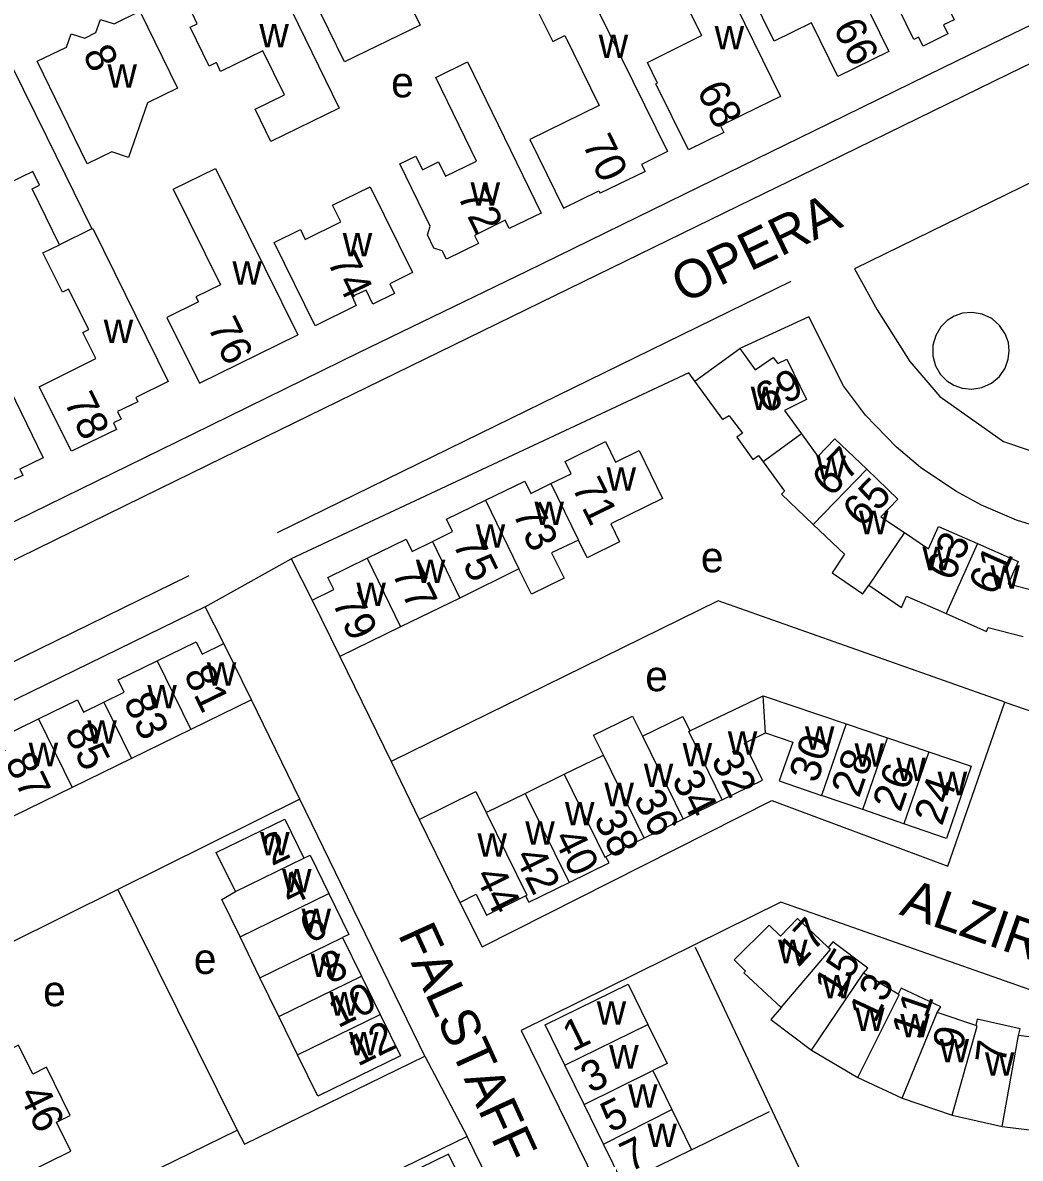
# Model space of a CAD drawing. Extents: x 159441 to 162086, y 388175 to 389787.
# Drawn here: x 161168.1 to 161298.8, y 389140.5 to 389289.4 of the extents above; entities that cross this region are included whole.
import ezdxf

# ---------------------------------------------------------------- set-up
doc = ezdxf.new("R2010")
doc.units = 0
for name, color, linetype in [('BLT_Basislijn', 7, 'Continuous'), ('BLT_Bebouwing', 7, 'Continuous'), ('BLT_Centroide', 7, 'Continuous'), ('BLT_Huisnummer', 7, 'Continuous'), ('BLT_Huisnummer_ tussenligend', 7, 'Continuous'), ('BLT_Huisnummer_reeks', 7, 'Continuous'), ('BLT_Onderverdeling_panden', 7, 'Continuous'), ('BLT_Straatnaam', 7, 'Continuous'), ('BLT_Vlakafsluiter', 7, 'Continuous')]:
    doc.layers.add(name, color=color, linetype=linetype)

msp = doc.modelspace()

# ---------------------------------------------------------------- linework, layer by layer
at = {"layer": 'BLT_Basislijn'}
for p, q in [((161201.47, 389222.55), (161268.78, 389255.48)), ((161216.38, 389192.52), (161220.02, 389184.92)), ((161256.18, 389168.15), (161275.7, 389126.74)), ((161220.77, 389153.85), (161226.34, 389143.34)), ((161255.73, 389141.61), (161265.95, 389146.61))]:
    msp.add_line(p, q, dxfattribs=at)
for points in [[(161323.97, 389300.63), (161318.56, 389298), (161310.41, 389294.03), (161297.83, 389287.9), (161288.73, 389283.48), (161273.69, 389276.11), (161254.7, 389266.85), (161234.08, 389256.77), (161212.19, 389246.11), (161190.3, 389235.4), (161162.94, 389222), (161151.75, 389216.52), (161143.27, 389212.36), (161140.82, 389211.17)], [(161140.82, 389211.17), (161141.32, 389210.26), (161142.12, 389209.17), (161142.71, 389208.49), (161143.97, 389207.61), (161153.84, 389212.52), (161186.03, 389228.29), (161194.27, 389232.34), (161235.94, 389252.69), (161261.89, 389265.34), (161273.46, 389270.99), (161297.32, 389282.66), (161308.2, 389287.97), (161328.14, 389297.72), (161329.19, 389298.24), (161330.33, 389298.66), (161331.64, 389299.08), (161333.15, 389299.34), (161334.55, 389299.5), (161335.85, 389299.5), (161337.31, 389299.35)], [(161356.55, 389242.65), (161339.94, 389276.6), (161339.22, 389277.83), (161338.54, 389278.75), (161337.48, 389279.77), (161336.36, 389280.67), (161334.32, 389281.67), (161332.32, 389282.19), (161330.34, 389282.27), (161328.28, 389281.94), (161326.76, 389281.41), (161277.06, 389257.08), (161280.07, 389251.72), (161284.35, 389244.96), (161288.25, 389240.35), (161296.6, 389234.45), (161306.3, 389231.2), (161315.37, 389230.18), (161324.36, 389231.75), (161328.63, 389233.02), (161339.19, 389236.54), (161356.55, 389242.65)], [(161297.36, 389246.34), (161297.24, 389247.44), (161296.83, 389248.59), (161296.1, 389249.69), (161295.06, 389250.58), (161293.8, 389251.17), (161292.48, 389251.39), (161291.22, 389251.27), (161290.14, 389250.89), (161289.23, 389250.32), (161288.39, 389249.48), (161287.72, 389248.38), (161287.35, 389247.07), (161287.34, 389245.68), (161287.71, 389244.37), (161288.36, 389243.26), (161289.2, 389242.42), (161290.11, 389241.84), (161291.19, 389241.46), (161292.44, 389241.33), (161293.77, 389241.54), (161295.03, 389242.11), (161296.07, 389243), (161296.82, 389244.09), (161297.23, 389245.24), (161297.36, 389246.34)], [(161377.7, 389141.03), (161398.49, 389150.98), (161358.19, 389233.53), (161324.94, 389222.58), (161320, 389221.7), (161315.37, 389221.36), (161310.96, 389221.46), (161306.93, 389221.92), (161302.1, 389222.95), (161298.33, 389224.14), (161293.71, 389226.11), (161290.34, 389227.93), (161285.72, 389231.07), (161282.57, 389233.73), (161278.51, 389237.91), (161275.64, 389241.75), (161271.11, 389250.82), (161262.06, 389246.64)], [(161256.17, 389242.38), (161255.39, 389243.46), (161203.26, 389219.06)], [(161203.26, 389219.06), (161206.03, 389213.65)], [(161100.59, 389173.15), (161115.84, 389180.62), (161189.89, 389216.88)], [(161191.99, 389212.77), (161117.83, 389176.55), (161130.41, 389150.79)], [(161194.44, 389207.98), (161191.99, 389212.77)], [(161296.77, 389200.28), (161259.21, 389213.58), (161216.38, 389192.52)], [(161209.65, 389206.25), (161216.38, 389192.52)], [(161204.39, 389187.56), (161198.06, 389200.58)], [(161225.36, 389174.03), (161228.3, 389168.2), (161266.25, 389187.37), (161289.33, 389178.76), (161296.77, 389200.28)], [(161296.77, 389200.28), (161311.63, 389195.19)], [(161204.39, 389187.56), (161180.56, 389175.71)], [(161220.77, 389153.85), (161204.39, 389187.56)], [(161180.56, 389175.71), (161130.41, 389150.79)], [(161180.56, 389175.71), (161196.2, 389144.16)], [(161329.32, 389134.03), (161317.5, 389156.46), (161267.42, 389174.06), (161233.39, 389157.24), (161255.69, 389111.86), (161258.43, 389113.03), (161264.05, 389102.15)], [(161197.16, 389142.32), (161220.77, 389153.85)], [(161145.7, 389119.49), (161196.2, 389144.16)], [(161196.2, 389144.16), (161197.16, 389142.32)], [(161226.34, 389143.34), (161201.39, 389131.17)], [(161231.96, 389069.61), (161256.48, 389081.57), (161226.34, 389143.34)]]:
    msp.add_lwpolyline(points, dxfattribs=at)
at = {"layer": 'BLT_Bebouwing'}
for p, q in [((161206.03, 389213.65), (161209.65, 389206.25)), ((161198.06, 389200.58), (161194.44, 389207.98)), ((161202.43, 389184.94), (161204.92, 389179.83)), ((161220.02, 389184.92), (161225.36, 389174.03)), ((161199.17, 389164.15), (161196.56, 389169.52)), ((161210.01, 389169.41), (161212.47, 389164.36)), ((161201.63, 389159.07), (161199.17, 389164.15)), ((161212.47, 389164.36), (161214.93, 389159.32)), ((161241.66, 389147.52), (161239.13, 389152.68)), ((161250.65, 389151.99), (161253.15, 389146.88)), ((161244.18, 389142.35), (161241.66, 389147.52))]:
    msp.add_line(p, q, dxfattribs=at)
for points in [[(161289.69, 389290.66), (161290.13, 389289.76), (161288.75, 389289.08), (161289.33, 389287.9), (161286.06, 389286.3), (161285.48, 389287.49), (161284.85, 389287.18), (161279.74, 389297.66), (161283.59, 389299.54), (161284.28, 389298.14), (161288.15, 389300.02), (161283.36, 389309.85), (161284.96, 389310.63), (161283.22, 389314.21), (161286.48, 389315.78)], [(161206.83, 389293), (161202.73, 389301.4), (161211.78, 389306.13), (161212.56, 389304.64), (161215.87, 389306.37), (161221.99, 389293.84), (161218.63, 389292.19), (161220.16, 389289.05), (161210.27, 389284.22), (161206.15, 389292.66), (161206.83, 389293)], [(161256.81, 389301.3), (161267.4, 389279.7), (161264.48, 389278.28), (161259.51, 389275.85), (161259.94, 389274.96), (161255.34, 389272.69), (161251.06, 389281.35), (161251.28, 389281.46), (161249.94, 389284.16), (161257.04, 389287.67)], [(161199.69, 389298.44), (161209.57, 389278.18), (161200.6, 389273.8), (161198.54, 389278.04), (161202.38, 389279.92), (161199.56, 389285.7), (161194.01, 389282.99), (161193.46, 389284.13), (161192.51, 389283.66), (161190.01, 389288.79), (161190.95, 389289.24), (161189.97, 389291.26), (161193.96, 389293.2), (161192.44, 389296.32), (161193.91, 389297.04), (161194.21, 389296.43), (161196.25, 389297.44), (161196.53, 389296.87), (161199.69, 389298.44)], [(161251.98, 389294.19), (161253.46, 389294.93), (161257.04, 389287.67)], [(161241.99, 389294), (161235.59, 389290.85), (161237.53, 389286.9), (161239.12, 389287.68), (161243.63, 389278.51), (161234.54, 389274.04), (161238.95, 389265.07), (161243.59, 389267.33), (161243.75, 389267)], [(161241.99, 389294), (161252.58, 389272.47), (161249.17, 389270.8), (161249.64, 389269.87), (161243.75, 389267)], [(161172.89, 389260.25), (161169.33, 389267.6), (161170.3, 389268.07), (161169.42, 389269.87), (161166.18, 389268.28), (161164.86, 389270.96), (161157.62, 389267.41), (161152.91, 389277.02), (161166.63, 389283.78), (161171.25, 389274.36), (161177.15, 389262.33)], [(161187.78, 389267.54), (161193.35, 389270.27), (161204.15, 389248.45)], [(161187.78, 389267.54), (161193.99, 389255.01), (161190.79, 389253.42), (161191.11, 389252.78), (161186.97, 389250.72), (161191.23, 389242.12), (161204.15, 389248.45)], [(161177.15, 389262.33), (161177.27, 389262.39), (161187.14, 389242.31), (161182.89, 389240.23), (161183.18, 389239.65), (161180.5, 389238.38), (161180.98, 389237.37), (161179.97, 389236.9), (161180.37, 389236.05), (161174.48, 389233.19), (161170.26, 389241.64), (161177.65, 389245.33), (161175.95, 389248.74), (161176.74, 389249.14), (161174.08, 389254.45), (161173.3, 389254.06), (161170.73, 389259.19), (161172.89, 389260.25)], [(161256.17, 389242.38), (161262.06, 389246.64)], [(161262.06, 389246.64), (161264.08, 389243.84)], [(161264.08, 389243.84), (161266.44, 389245.48), (161267.05, 389244.69), (161268.22, 389245.27), (161270.81, 389239.96), (161267.92, 389238.54), (161270.15, 389235.45)], [(161260.64, 389237.84), (161259.83, 389237.36), (161256.17, 389242.38)], [(161260.64, 389237.84), (161262.4, 389235.57), (161261.67, 389235.04), (161263.78, 389232.11), (161264.51, 389232.64), (161265.12, 389231.79)], [(161270.15, 389235.45), (161272.29, 389232.5), (161274.52, 389234.82), (161278.68, 389230.83)], [(161237.3, 389228.94), (161239.95, 389230.24), (161239.16, 389231.86), (161244.45, 389234.47), (161245.77, 389231.76), (161248.86, 389233.27), (161251.93, 389226.97), (161245.14, 389223.65), (161246.28, 389221.3), (161242.03, 389219.22), (161240.92, 389221.54)], [(161265.12, 389231.79), (161267.91, 389227.94), (161267.53, 389227.54), (161271.68, 389223.58)], [(161278.68, 389230.83), (161282.76, 389226.92), (161280.53, 389224.59), (161283.62, 389222.51)], [(161228.74, 389226.76), (161233.86, 389229.26), (161234.65, 389227.65), (161237.3, 389228.94)], [(161221.76, 389221.34), (161224.41, 389222.64), (161223.62, 389224.26), (161228.74, 389226.76)], [(161271.68, 389223.58), (161275.79, 389219.67), (161274.17, 389217.22), (161278.18, 389214.48), (161278.95, 389215.61)], [(161283.62, 389222.51), (161286.79, 389220.38), (161288.08, 389223.32), (161293.19, 389221.07)], [(161213.2, 389219.16), (161218.32, 389221.66), (161219.11, 389220.05), (161221.76, 389221.34)], [(161240.92, 389221.54), (161237.38, 389219.85), (161239.03, 389216.55), (161234.77, 389214.43), (161233.11, 389217.77)], [(161293.19, 389221.07), (161298.52, 389218.73), (161297.22, 389215.78), (161300.67, 389214.91)], [(161206.03, 389213.65), (161208.87, 389215.04), (161208.08, 389216.65), (161213.2, 389219.16)], [(161233.11, 389217.77), (161225.38, 389213.94)], [(161278.95, 389215.61), (161283.25, 389212.7), (161283.9, 389214.17), (161289.1, 389211.89)], [(161225.38, 389213.94), (161217.61, 389210.14)], [(161289.1, 389211.89), (161294.37, 389209.57), (161294.59, 389210.07), (161299.17, 389208.91)], [(161217.61, 389210.14), (161209.65, 389206.25)], [(161185.69, 389205.71), (161190.81, 389208.21), (161191.6, 389206.59), (161194.44, 389207.98)], [(161178.71, 389200.29), (161181.36, 389201.58), (161180.57, 389203.2), (161185.69, 389205.71)], [(161170.15, 389198.1), (161175.27, 389200.61), (161176.06, 389198.99), (161178.71, 389200.29)], [(161198.06, 389200.58), (161190.1, 389196.68)], [(161255.51, 389196.53), (161265.13, 389201.13)], [(161265.13, 389201.13), (161276.01, 389197.44)], [(161163.17, 389192.69), (161165.82, 389193.98), (161165.03, 389195.6), (161170.15, 389198.1)], [(161244.19, 389193.34), (161242.9, 389195.97), (161248.01, 389198.47), (161249.3, 389195.84)], [(161249.3, 389195.84), (161254.59, 389198.42), (161255.51, 389196.53)], [(161190.1, 389196.68), (161182.33, 389192.89)], [(161259.73, 389187.46), (161265.03, 389190.07), (161262.65, 389194.92), (161265.42, 389196.27)], [(161265.42, 389196.27), (161268.98, 389195.06), (161267.23, 389189.95), (161272.76, 389188.06)], [(161276.01, 389197.44), (161281.4, 389195.61)], [(161281.4, 389195.61), (161286.81, 389193.78)], [(161239.05, 389190.83), (161244.19, 389193.34)], [(161286.81, 389193.78), (161292.38, 389191.89), (161289.14, 389182.43), (161283.56, 389184.35)], [(161182.33, 389192.89), (161174.56, 389189.09)], [(161233.93, 389188.32), (161239.05, 389190.83)], [(161174.56, 389189.09), (161166.79, 389185.28)], [(161220.02, 389184.92), (161227.46, 389188.56), (161228.81, 389185.81)], [(161228.81, 389185.81), (161233.93, 389188.32)], [(161259.73, 389187.46), (161254.62, 389184.96)], [(161278.19, 389186.2), (161272.76, 389188.06)], [(161283.56, 389184.35), (161278.19, 389186.2)], [(161195.95, 389175.45), (161193.45, 389180.56), (161202.43, 389184.94)], [(161254.62, 389184.96), (161249.5, 389182.46)], [(161249.5, 389182.46), (161244.51, 389180.02)], [(161204.92, 389179.83), (161205.75, 389180.24), (161208.21, 389175.2)], [(161239.67, 389176.65), (161244.94, 389179.23), (161244.51, 389180.02)], [(161196.56, 389169.52), (161194.17, 389174.41), (161195.95, 389175.45)], [(161233.98, 389174.88), (161234.39, 389174.07), (161239.67, 389176.65)], [(161208.21, 389175.2), (161210.84, 389169.81), (161210.01, 389169.41)], [(161225.36, 389174.03), (161227.51, 389175.09), (161228.85, 389172.37), (161233.98, 389174.88)], [(161273.64, 389168.12), (161271.69, 389169.96), (161269.61, 389171.9), (161267.37, 389169.6), (161265.89, 389171.06), (161261.32, 389166.48), (161262.8, 389165.01), (161262.57, 389164.78), (161267.49, 389160.25)], [(161278.25, 389164.75), (161278.83, 389165.42), (161274.24, 389168.85), (161273.64, 389168.12)], [(161239.13, 389152.68), (161236.54, 389157.98), (161247.43, 389163.3)], [(161247.43, 389163.3), (161250.01, 389158.03)], [(161282.79, 389162), (161278.25, 389164.75)], [(161287.91, 389159.59), (161288.39, 389160.36), (161283.18, 389162.8), (161282.79, 389162)], [(161204.11, 389154.03), (161201.63, 389159.07)], [(161214.93, 389159.32), (161217.58, 389153.9), (161206.74, 389148.63), (161204.11, 389154.03)], [(161267.49, 389160.25), (161266.13, 389158.66), (161271.44, 389154.65)], [(161292.97, 389157.88), (161287.91, 389159.59)], [(161250.01, 389158.03), (161252.53, 389152.9), (161250.65, 389151.99)], [(161298.58, 389156.58), (161298.8, 389157.46), (161293.17, 389158.74), (161292.97, 389157.88)], [(161303.8, 389155.93), (161298.58, 389156.58)], [(161167.54, 389155.33), (161158.12, 389150.72), (161156.98, 389153.06), (161146.72, 389148.04), (161147.86, 389145.7), (161138.44, 389141.09), (161140.31, 389137.28), (161138.48, 389136.39), (161141.56, 389130.1), (161143.38, 389130.99), (161145.24, 389127.18), (161154.67, 389131.77), (161155.1, 389130.9), (161165.37, 389135.91), (161164.94, 389136.79), (161174.37, 389141.41), (161172.5, 389145.22), (161174.31, 389146.1), (161171.22, 389152.41), (161169.41, 389151.52), (161167.54, 389155.33)], [(161271.44, 389154.65), (161277.52, 389151.07)], [(161277.52, 389151.07), (161283.33, 389148.38)], [(161283.33, 389148.38), (161289.87, 389146.15)], [(161253.15, 389146.88), (161255.73, 389141.61), (161246.71, 389137.19), (161244.18, 389142.35)], [(161289.87, 389146.15), (161296.44, 389144.64)], [(161296.44, 389144.64), (161303.26, 389143.82), (161303.52, 389145.92)], [(161226.49, 389135.74), (161223.9, 389141.04), (161213.04, 389135.75), (161215.24, 389131.26)]]:
    msp.add_lwpolyline(points, dxfattribs=at)
for points in [[(161271.58, 389308.51), (161276.39, 389298.75), (161274.81, 389297.97), (161277.27, 389292.93), (161277.87, 389293.22), (161281.59, 389285.59), (161274.89, 389282.32), (161271.44, 389289.36), (161266.54, 389286.97), (161263.52, 389293.13), (161269.18, 389295.9), (161267.61, 389299.12), (161268.62, 389299.62), (161265.68, 389305.63)], [(161183.44, 389290.88), (161188.38, 389280.8), (161184.43, 389278.88), (161181.93, 389271.7), (161179.78, 389272.45), (161176.54, 389270.87), (161169.98, 389284.31), (161173.84, 389286.18), (161174.44, 389287.92), (161176.22, 389287.36), (161177.67, 389288.07), (161178.29, 389289.81), (161180.07, 389289.24)], [(161226.39, 389284.22), (161236, 389264.4), (161231.85, 389262.38), (161231.32, 389263.46), (161227.28, 389261.48), (161227.81, 389260.4), (161223.63, 389258.35), (161223.07, 389259.48), (161221.97, 389259.81), (161221.11, 389261.56), (161221.49, 389262.69), (161217.52, 389270.88), (161219.61, 389271.89), (161220.48, 389270.09), (161222.58, 389271.11), (161223.47, 389269.26), (161227.54, 389271.23), (161222.22, 389282.19)], [(161213.62, 389267.86), (161219.15, 389256.62), (161216.17, 389255.15), (161216.81, 389253.86), (161213.96, 389252.46), (161213.08, 389254.32), (161211.25, 389253.45), (161211.8, 389252.29), (161206.41, 389249.61), (161201.02, 389260.56), (161204.47, 389262.26), (161205.11, 389260.96), (161209.77, 389263.25), (161208.69, 389265.43)], [(161164.21, 389245.75), (161170.77, 389232.31), (161167.71, 389230.82), (161168.11, 389230.01), (161162.24, 389227.49), (161158.07, 389225.48), (161152.95, 389235.95), (161160.77, 389239.77), (161159.07, 389243.24)]]:
    msp.add_lwpolyline(points, close=True, dxfattribs=at)
at = {"layer": 'BLT_Onderverdeling_panden'}
for p, q in [((161177.15, 389262.33), (161172.89, 389260.25)), ((161270.15, 389235.45), (161265.12, 389231.79)), ((161278.68, 389230.83), (161271.68, 389223.58)), ((161237.3, 389228.94), (161240.92, 389221.54)), ((161228.74, 389226.76), (161233.11, 389217.77)), ((161283.62, 389222.51), (161278.95, 389215.61)), ((161221.76, 389221.34), (161225.38, 389213.94)), ((161293.19, 389221.07), (161289.1, 389211.89)), ((161213.2, 389219.16), (161217.61, 389210.14)), ((161185.69, 389205.71), (161190.1, 389196.68)), ((161265.42, 389196.27), (161265.13, 389201.13)), ((161178.71, 389200.29), (161182.33, 389192.89)), ((161170.15, 389198.1), (161174.56, 389189.09)), ((161276.01, 389197.44), (161272.76, 389188.06)), ((161249.3, 389195.84), (161254.62, 389184.96)), ((161278.19, 389186.2), (161281.4, 389195.61)), ((161249.5, 389182.46), (161244.19, 389193.34)), ((161286.81, 389193.78), (161283.56, 389184.35)), ((161233.93, 389188.32), (161239.67, 389176.65)), ((161195.95, 389175.45), (161204.92, 389179.83)), ((161196.56, 389169.52), (161208.21, 389175.2)), ((161199.17, 389164.15), (161210.01, 389169.41)), ((161201.63, 389159.07), (161212.47, 389164.36)), ((161204.11, 389154.03), (161214.93, 389159.32)), ((161239.13, 389152.68), (161250.01, 389158.03)), ((161296.44, 389144.64), (161298.58, 389156.58)), ((161241.66, 389147.52), (161250.65, 389151.99)), ((161244.18, 389142.35), (161253.15, 389146.88))]:
    msp.add_line(p, q, dxfattribs=at)
for points in [[(161259.73, 389187.46), (161255.35, 389196.45), (161255.51, 389196.53)], [(161239.05, 389190.83), (161244.37, 389179.95), (161244.51, 389180.02)], [(161228.81, 389185.81), (161234.15, 389174.96), (161233.98, 389174.88)], [(161267.49, 389160.25), (161273.92, 389167.86), (161273.64, 389168.12)], [(161271.44, 389154.65), (161278.25, 389164.75)], [(161277.52, 389151.07), (161282.94, 389161.91), (161282.79, 389162)], [(161283.33, 389148.38), (161287.91, 389159.59)], [(161289.87, 389146.15), (161293.14, 389157.82), (161292.97, 389157.88)]]:
    msp.add_lwpolyline(points, dxfattribs=at)
at = {"layer": 'BLT_Vlakafsluiter'}
msp.add_line((161191.99, 389212.77), (161203.26, 389219.06), dxfattribs=at)

# ---------------------------------------------------------------- texts
at = {"layer": 'BLT_Centroide'}
for s, p in [('w', (161199.09, 389286.12)), ('w', (161258.75, 389285.86)), ('w', (161243.56, 389284.73)), ('w', (161179.19, 389280.84)), ('e', (161216.36, 389279.58)), ('w', (161226.77, 389265.36)), ('w', (161210.02, 389258.72)), ('w', (161195.56, 389255.03)), ('w', (161178.7, 389247.36)), ('w', (161263.48, 389238.59)), ('w', (161272.09, 389229.53)), ('w', (161244.59, 389228)), ('w', (161235.14, 389223.5)), ('w', (161277.66, 389222.31)), ('w', (161227.45, 389220.55)), ('e', (161256.95, 389217.31)), ('w', (161285.98, 389217.59)), ('w', (161219.6, 389215.91)), ('w', (161294.89, 389215.17)), ('w', (161211.81, 389212.89)), ('w', (161192.21, 389202.44)), ('e', (161249.66, 389201.72)), ('w', (161184.41, 389199.48)), ('w', (161176.55, 389194.84)), ('w', (161260.48, 389193.38)), ('w', (161270.59, 389194.05)), ('w', (161168.86, 389191.89)), ('w', (161254.56, 389191.86)), ('w', (161277.09, 389191.81)), ('w', (161249.47, 389189.17)), ('w', (161282.55, 389189.95)), ('w', (161287.98, 389188.09)), ('w', (161244.31, 389186.64)), ('w', (161239.14, 389184.12)), ('w', (161233.94, 389181.58)), ('w', (161199.19, 389180.19)), ('w', (161227.67, 389180.02)), ('w', (161202.07, 389175.34)), ('w', (161204.62, 389170.12)), ('e', (161190.5, 389164.65)), ('w', (161267.06, 389166.06)), ('w', (161205.82, 389164.25)), ('e', (161170.76, 389160.42)), ('w', (161272.84, 389161.45)), ('w', (161208.29, 389159.19)), ('w', (161243.3, 389158)), ('w', (161277.17, 389157.17)), ('w', (161283.08, 389156.33)), ('w', (161210.84, 389153.97)), ('w', (161288.23, 389153.06)), ('w', (161244.93, 389152.25)), ('w', (161294.17, 389151.31)), ('w', (161247.41, 389147.12)), ('w', (161249.94, 389141.97))]:
    msp.add_text(s, height=4, dxfattribs=at).set_placement(p)
at = {"layer": 'BLT_Huisnummer'}
for s, rotation, p in [('66', 296.0658, (161274.22, 389288.74)), ('8', 296.0768, (161175.89, 389285.27)), ('68', 296.015, (161256.35, 389280.54)), ('70', 296.015, (161241.34, 389273.51)), ('72', 296.015, (161224.97, 389266.73)), ('74', 296.015, (161207.92, 389258.08)), ('76', 296.015, (161192.23, 389249.55)), ('69', 26.0648, (161265.34, 389238.02)), ('78', 296.015, (161173.43, 389239.71)), ('71', 296.0596, (161239.98, 389228.52)), ('65', 46.0422, (161278.02, 389223.04)), ('75', 296.0596, (161224.37, 389221.08)), ('61', 65.9958, (161295.51, 389214.11)), ('79', 296.0596, (161208.55, 389213.38)), ('81', 296.0613, (161189.11, 389203.99)), ('85', 296.0613, (161173.51, 389196.33)), ('32', 296.2661, (161258.21, 389192.76)), ('28', 71.0633, (161277.67, 389187.61)), ('24', 71.0633, (161288.54, 389183.95)), ('36', 296.2661, (161248.05, 389187.63)), ('2', 26.0108, (161200.74, 389178.76)), ('40', 296.2661, (161237.55, 389182.49)), ('44', 296.2661, (161227.26, 389177.55)), ('6', 26.0108, (161205.68, 389168.57)), ('17', 47.067, (161269.61, 389165.3)), ('13', 65.0648, (161279.82, 389158.07)), ('12', 26.0108, (161211.98, 389152.47)), ('1', 26.0551, (161240.12, 389154.39)), ('9', 77.0715, (161291.14, 389154.37)), ('7', 26.0551, (161247.63, 389138.61))]:
    msp.add_text(s, height=4, rotation=rotation, dxfattribs=at).set_placement(p)
at = {"layer": 'BLT_Huisnummer_ tussenligend'}
for s, rotation, p in [('67', 46.0422, (161274.01, 389227.05)), ('73', 296.0596, (161232.21, 389225.07)), ('63', 65.9915, (161289.94, 389215.98)), ('77', 296.0596, (161216.38, 389217.24)), ('83', 296.0613, (161181.21, 389200.36)), ('30', 71.0633, (161272.16, 389189.53)), ('87', 296.0613, (161165.71, 389192.49)), ('26', 71.0633, (161283.1, 389185.74)), ('34', 296.2661, (161253.06, 389190.17)), ('38', 296.2661, (161242.84, 389184.95)), ('42', 296.2661, (161232.48, 389180.08)), ('4', 26.0108, (161203.11, 389173.52)), ('8', 26.0108, (161208.34, 389163.25)), ('15', 59.0688, (161274.98, 389161.27)), ('10', 26.0108, (161209.4, 389157.51)), ('11', 71.0615, (161285.55, 389155.88)), ('7', 83.0637, (161296.85, 389152.75)), ('3', 26.0551, (161242.47, 389148.96)), ('5', 26.0551, (161245.09, 389143.79))]:
    msp.add_text(s, height=4, rotation=rotation, dxfattribs=at).set_placement(p)
at = {"layer": 'BLT_Huisnummer_reeks'}
msp.add_text('46', height=4, rotation=296.0548, dxfattribs=at).set_placement((161167.51, 389148.88))
at = {"layer": 'BLT_Straatnaam'}
for s, rotation, p in [('OPERA', 25.8394, (161254.69, 389252.5)), ('ALZIRA', 340.8085, (161282.83, 389172.49)), ('FALSTAFF', 294.5309, (161217.2, 389169.86))]:
    msp.add_text(s, height=5, rotation=rotation, dxfattribs=at).set_placement(p)

doc.saveas('drawing.dxf')
